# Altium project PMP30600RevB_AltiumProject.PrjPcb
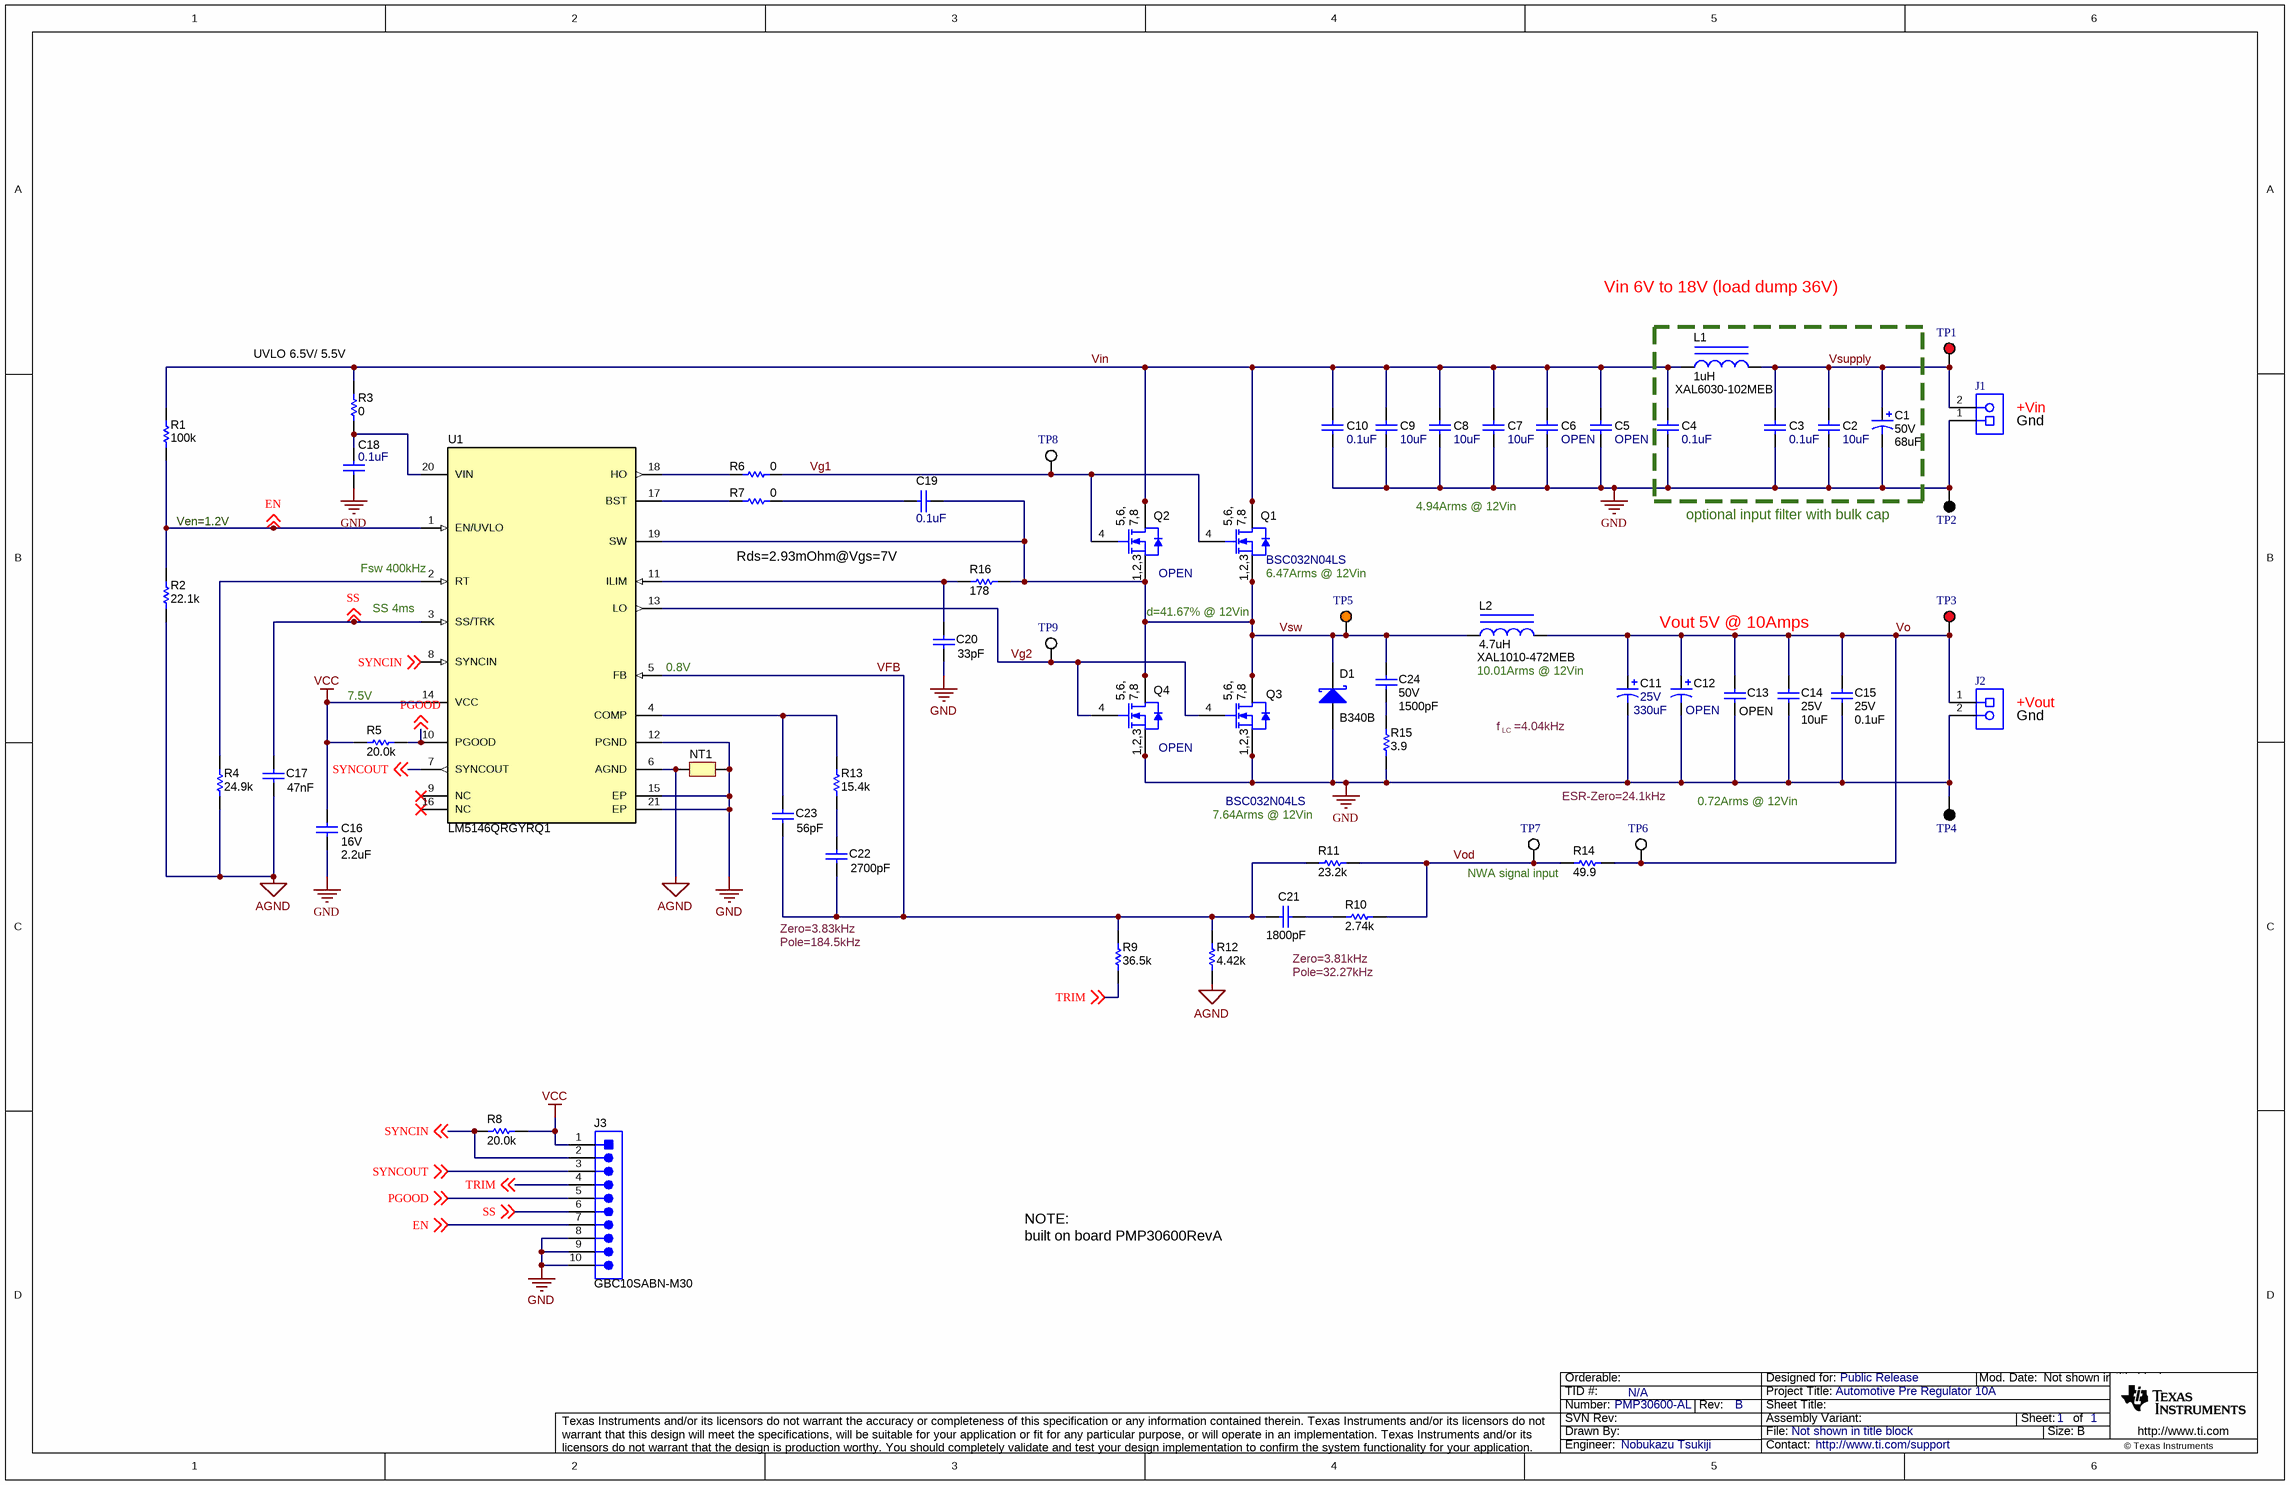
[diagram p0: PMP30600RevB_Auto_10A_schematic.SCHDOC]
TID: N/A; TechSupport: http://www.ti.com/support; SCH_Rev: B; PRJ_Title: Automotive Pre Regulator 10A; PRJ_Number: PMP30600-AL; PRJ_Engineer: Nobukazu Tsukiji; PRJ_Customer: Public Release; PCB_Rev: A; PCB_Layout: Who did the Layout?
1 sheet, 61 parts. Net scope: global (net labels, ports and power ports of the same name join across sheets).
Board file: PMP30600RevA_board.PcbDoc

## Sheet PMP30600RevB_Auto_10A_schematic.SCHDOC
size 431 x 279 mm; Date: Not shown in title block; ApprovedBy: Not shown in title block; CheckedBy: Not shown in title block; Author: Not shown in title block; CompanyName: Not shown in title block; Engineer: Not shown in title block; Organization: Not shown in title block; Address1: Not shown in title block; Address2: Not shown in title block; Address3: Not shown in title block; Address4: Not shown in title block; DocumentNumber: 1; Revision: Use project parameter SCH_Rev; SheetNumber: 1; SheetTotal: 1; PageSetup: Record=PageOptions¦CenterHorizontal=True¦CenterVertical=True¦PrintScale=0.70¦XCorrection=1.00¦YCorrection=1.00¦PrintKind=0¦BorderSize=5000000¦LeftOffset=0¦BottomOffset=0¦Orientation=2¦PaperLength=1000¦PaperWidth=1000¦Scale=100¦PaperSource=15¦PrintQuality=600¦MediaType=1¦DitherType=10¦PaperKind=A4¦PrintScaleMode=1

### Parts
C1  VDC_V: 50V  ValueDisplayed: 68uF  [SM_RADIAL_8MM]  (hidden comment: EEHZC1H680P)
C2  ValueDisplayed: 10uF  [1210_270]  (hidden comment: Capacitor)
C3  ValueDisplayed: 0.1uF  [0603]  (hidden comment: Capacitor)
C4  ValueDisplayed: 0.1uF  [0603]  (hidden comment: Capacitor)
C5  ValueDisplayed: OPEN  [1210_270]  (hidden comment: Capacitor)
C6  ValueDisplayed: OPEN  [1210_270]  (hidden comment: Capacitor)
C7  ValueDisplayed: 10uF  [1210_270]  (hidden comment: Capacitor)
C8  ValueDisplayed: 10uF  [1210_270]  (hidden comment: Capacitor)
C9  ValueDisplayed: 10uF  [1210_270]  (hidden comment: Capacitor)
C10  ValueDisplayed: 0.1uF  [0603]  (hidden comment: Capacitor)
C11  VDC_V: 25V  ValueDisplayed: 330uF  [SM_RADIAL_10BMM]  (hidden comment: EEHZC1E331P)
C12  ValueDisplayed: OPEN  [SM_RADIAL_10BMM]  (hidden comment: EEHZC1E331P)
C13  VDC_V: OPEN  [1210_220]  (hidden comment: GRM32DR71E106KA12L)
C14  VDC_V: 25V  ValueDisplayed: 10uF  [1210_220]  (hidden comment: GRM32DR71E106KA12L)
C15  VDC_V: 25V  ValueDisplayed: 0.1uF  [0603]  (hidden comment: GRM188R71E104KA01D)
C16  VDC_V: 16V  ValueDisplayed: 2.2uF  [0805_HV]  (hidden comment: GRM21BR71C225KA12L)
C17  ValueDisplayed: 47nF  [0603]  (hidden comment: GRM188R71E473KA01D)
C18  ValueDisplayed: 0.1uF  [0603]  (hidden comment: Capacitor)
C19  ValueDisplayed: 0.1uF  [0603]  (hidden comment: Capacitor)
C20  ValueDisplayed: 33pF  [0603]  (hidden comment: GRM1885C1H330JA01D)
C21  ValueDisplayed: 1800pF  [0603]  (hidden comment: GRM1885C1H182JA01D)
C22  ValueDisplayed: 2700pF  [0603]  (hidden comment: GRM1885C1H272JA01D)
C23  ValueDisplayed: 56pF  [0603]  (hidden comment: GRM1885C1H560JA01D)
C24  VDC_V: 50V  ValueDisplayed: 1500pF  [0603]  (hidden comment: GRM188R71H152KA01D)
D1  PartNumberDisplayed: B340B  [SMB]  (hidden comment: B340B-13-F)
J1  691214110002  [Wurth_691214110002]  (value not drawn)
J2  691236510002  [Wurth_691236510002]  (value not drawn)
J3  GBC10SABN-M30  [Sullins_GBC10SABN-M30]
L1  XAL6030-102MEB  ValueDisplayed: 1uH  [XAL6030]
L2  XAL1010-472MEB  ValueDisplayed: 4.7uH  [XAL1010]
NT1  Net-Tie  [Net-Tie_10milWide_30milLong]  (value not drawn)  (net tie, no BOM)
Q1  BSC032N04LS  [PG-TDSON-8]
Q2  OPEN  [PG-TDSON-8]
Q3  PartNumber: BSC032N04LS  [PG-TDSON-8]  (hidden comment: MOSFET_N_D56789G4S123)
Q4  OPEN  [PG-TDSON-8]
R1  ValueDisplayed: 100k  [0603]  (hidden comment: CRCW0603100KFKEA)
R2  ValueDisplayed: 22.1k  [0603]  (hidden comment: CRCW060322K1FKEA)
R3  ValueDisplayed: 0  [0603]  (hidden comment: RMCF0603ZT0R00)
R4  ValueDisplayed: 24.9k  [0603]  (hidden comment: CRCW060324K9FKEA)
R5  ValueDisplayed: 20.0k  [0603]  (hidden comment: CRCW060320K0FKEA)
R6  ValueDisplayed: 0  [0603]  (hidden comment: RMCF0603ZT0R00)
R7  ValueDisplayed: 0  [0603]  (hidden comment: RMCF0603ZT0R00)
R8  ValueDisplayed: 20.0k  [0603]  (hidden comment: CRCW060320K0FKEA)
R9  ValueDisplayed: 36.5k  [0603]  (hidden comment: RC0603FR-0736K5L)
R10  ValueDisplayed: 2.74k  [0603]  (hidden comment: CRCW06032K74FKEA)
R11  ValueDisplayed: 23.2k  [0603]  (hidden comment: CRCW060323K2FKEA)
R12  ValueDisplayed: 4.42k  [0603]  (hidden comment: CRCW06034K42FKEA)
R13  ValueDisplayed: 15.4k  [0603]  (hidden comment: CRCW060315K4FKEA)
R14  ValueDisplayed: 49.9  [0603]  (hidden comment: CRCW060349R9FKEA)
R15  ValueDisplayed: 3.9  [0805_HV]  (hidden comment: CRCW08053R90JNEA)
R16  ValueDisplayed: 178  [0603]  (hidden comment: CRCW0603178RFKEA)
TP1  5000  [Keystone5000]  (value not drawn)
TP2  5001  [Keystone5001]  (value not drawn)
TP3  5000  [Keystone5000]  (value not drawn)
TP4  5001  [Keystone5001]  (value not drawn)
TP5  5003  [Keystone5003]  (value not drawn)
TP6  5002  [Keystone5002]  (value not drawn)
TP7  5002  [Keystone5002]  (value not drawn)
TP8  5002  [Keystone5002]  (value not drawn)
TP9  5002  [Keystone5002]  (value not drawn)
U1  LM5146QRGYRQ1  [RGY0020B]

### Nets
AGND: C17.2 NT1.1 R2.1 R4.1 R12.1 U1.6(AGND)
GND: C1.2(-) C2.2 C3.2 C4.2 C5.2 C6.2 C7.2 C8.2 C9.2 C10.2 C11.2(-) C12.2(-) C13.2 C14.2 C15.2 C16.2 C18.2 C20.2 D1.2(A) J1.1 J2.2 J3.8 J3.9 J3.10 NT1.2 Q3.1(S) Q3.2(S) Q3.3(S) Q4.1(S) Q4.2(S) Q4.3(S) R15.1 TP2.1 TP4.1 U1.12(PGND) U1.15(EP) U1.21(EP)
VCC: C16.1 J3.1 R5.1 R8.2 U1.14(VCC)
EN: J3.7 R1.1 R2.2 U1.1(EN/UVLO) ; off-sheet EN
PGOOD: J3.5 R5.2 U1.10(PGOOD) ; off-sheet PGOOD
SS: C17.1 J3.6 U1.3(SS/TRK) ; off-sheet SS
SYNCIN: J3.2 R8.1 U1.8(SYNCIN) ; off-sheet SYNCIN
SYNCOUT: J3.3 U1.7(SYNCOUT) ; off-sheet SYNCOUT
TRIM: J3.4 R9.1 ; off-sheet TRIM
VFB: C21.2 C22.1 C23.1 R9.2 R11.1 R12.2 U1.5(FB)
Vg1: Q1.4(G) Q2.4(G) R6.2 TP8.1
Vg2: Q3.4(G) Q4.4(G) TP9.1 U1.13(LO)
Vin: C4.1 C5.1 C6.1 C7.1 C8.1 C9.1 C10.1 L1.1 Q1.5(D) Q1.6(D) Q1.7(D) Q1.8(D) Q1.9(D) Q2.5(D) Q2.6(D) Q2.7(D) Q2.8(D) Q2.9(D) R1.2 R3.2
Vo: C11.1(+) C12.1(+) C13.1 C14.1 C15.1 J2.1 L2.2 R14.2 TP3.1 TP6.1
Vod: R10.2 R11.2 R14.1 TP7.1
Vsupply: C1.1(+) C2.1 C3.1 J1.2 L1.2 TP1.1
Vsw: C19.2 C24.1 D1.1(K) L2.1 Q1.1(S) Q1.2(S) Q1.3(S) Q2.1(S) Q2.2(S) Q2.3(S) Q3.5(D) Q3.6(D) Q3.7(D) Q3.8(D) Q3.9(D) Q4.5(D) Q4.6(D) Q4.7(D) Q4.8(D) Q4.9(D) R16.2 TP5.1 U1.19(SW)
NetC18_1: C18.1 R3.1 U1.20(VIN)
NetC19_1: C19.1 R7.2
NetC20_1: C20.1 R16.1 U1.11(ILIM)
NetC21_1: C21.1 R10.1
NetC22_2: C22.2 R13.2
NetC23_2: C23.2 R13.1 U1.4(COMP)
NetC24_2: C24.2 R15.2
NetR4_2: R4.2 U1.2(RT)
NetR6_1: R6.1 U1.18(HO)
NetR7_1: R7.1 U1.17(BST)

Not connected (* = marked no-connect by the designer): U1 9(NC)* 16(NC)*

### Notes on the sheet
- Vin 6V to 18V (load dump 36V)
- (near R3) UVLO 6.5V/ 5.5V
- (near J1) +Vin
- (near J1) Gnd
- Ven=1.2V
- (near U1) Fsw 400kHz
- Rds=2.93mOhm@Vgs=7V
  ILIM=13A
- 4.94Arms @ 12Vin
- (near TP2) optional input filter with bulk cap
- (near U1) SS 4ms
- d=41.67% @ 12Vin
- (near Q1) 6.47Arms @ 12Vin
- Vout 5V @ 10Amps
- (near R5) 7.5V
- (near U1) 0.8V
- (near L2) 10.01Arms @ 12Vin
- (near J2) +Vout
- LC
- f    =4.04kHz
- (near J2) Gnd
- (near R11) 7.64Arms @ 12Vin
- ESR-Zero=24.1kHz
- 0.72Arms @ 12Vin
- NWA signal input
- Zero=3.83kHz
- Pole=184.5kHz
- Zero=3.81kHz
- Pole=32.27kHz
- built on board PMP30600RevA
- NOTE:

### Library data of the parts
C1 = CMP-0012599-3: CAP, Polymer Hybrid, 68 uF, 50 V, +/- 20%, 30 ohm, 8x10 SMD; Manufacturer: Panasonic; TaMin_C: -55°C; ESR_ohm: 30; Polarized: Y; SizeAreaWB_mm2: 113.3; Value1: 30 ohm; Value: 68uF; TaMax_C: 125°C; SizeZ_mm: 10.2; SizeX_mm: 9; SizeY_mm: 8.3; SizeArea_mm2: 74.7; CompType: Capacitor; Cap_F: 68µF; IRMS_A: 1.25A; AEC Category: Q200
C2 C5-C9 = CMP-0009226-3: CAP, CERM, 10 uF, 50 V, +/- 10%, X7R, 1210; PartNumber: GRM32ER71H106KA12L; Manufacturer: MuRata; Polarized: N; Value: 10uF; U/M: EA; Cap_F: 10µF; Value1: Unknown; VDC_V: 50V; TaMin_C: -55°C; TaMax_C: 125°C; Cap_Case: 1210; SizeArea_mm2: 8; SizeAreaWB_mm2: 14.7; SizeX_mm: 3.2; SizeY_mm: 2.5; SizeZ_mm: 2.7; AEC Category: Q200
C3 C4 C10 C18 C19 = CMP-0007434-4: CAP, CERM, 0.1 uF, 50 V, +/- 10%, X7R, 0603; PartNumber: GRM188R71H104KA93D; Manufacturer: MuRata; Polarized: N; Value: 0.1uF; U/M: EA; Cap_F: 100nF; Value1: Unknown; VDC_V: 50V; TaMin_C: -55°C; TaMax_C: 125°C; SizeArea_mm2: 1.28; SizeAreaWB_mm2: 4.68; SizeX_mm: 1.6; SizeY_mm: 0.8; SizeZ_mm: 1; AEC Category: Q200
C11 = CMP-0012593-1: CAP, Polymer Hybrid, 330 uF, 25 V, +/- 20%, 20 ohm, 10x10 SMD; Manufacturer: Panasonic; TaMin_C: -55°C; ESR_ohm: 20; Polarized: Y; SizeAreaWB_mm2: 159.9; Value1: 20 ohm; U/M: EA; Value: 330uF; TaMax_C: 125°C; SizeZ_mm: 10.2; SizeX_mm: 11; SizeY_mm: 10.3; SizeArea_mm2: 113.3; CompType: Capacitor; Cap_F: 330µF; IRMS_A: 2A; AEC Category: Q200
C12 = CMP-0012593-1: CAP, Polymer Hybrid, 330 uF, 25 V, +/- 20%, 20 ohm, 10x10 SMD; Manufacturer: Panasonic; TaMin_C: -55°C; ESR_ohm: 20; Polarized: Y; SizeAreaWB_mm2: 159.9; Value1: 20 ohm; U/M: EA; Value: 330uF; TaMax_C: 125°C; SizeZ_mm: 10.2; SizeX_mm: 11; SizeY_mm: 10.3; Value2: 25V; SizeArea_mm2: 113.3; CompType: Capacitor; Cap_F: 330µF; IRMS_A: 2A; AEC Category: Q200
C13 = CMP-0009190-1: CAP, CERM, 10 uF, 25 V, +/- 10%, X7R, 1210; Manufacturer: MuRata; TaMin_C: -55°C; Polarized: N; SizeAreaWB_mm2: 14.7; Value1: Unknown; U/M: EA; Value: 10uF; TaMax_C: 125°C; SizeZ_mm: 2.2; SizeX_mm: 3.2; SizeY_mm: 2.5; Cap_Case: 1210; Value2: 25V; SizeArea_mm2: 8; Cap_F: 10µF; AEC Category: Q200
C14 = CMP-0009190-1: CAP, CERM, 10 uF, 25 V, +/- 10%, X7R, 1210; Manufacturer: MuRata; TaMin_C: -55°C; Polarized: N; SizeAreaWB_mm2: 14.7; Value1: Unknown; U/M: EA; Value: 10uF; TaMax_C: 125°C; SizeZ_mm: 2.2; SizeX_mm: 3.2; SizeY_mm: 2.5; Cap_Case: 1210; SizeArea_mm2: 8; Cap_F: 10µF; AEC Category: Q200
C15 = CMP-0007404-4: CAP, CERM, 0.1 uF, 25 V, +/- 10%, X7R, 0603; Manufacturer: MuRata; TaMin_C: -55°C; Polarized: N; SizeAreaWB_mm2: 4.68; Value1: Unknown; U/M: EA; Value: 0.1uF; TaMax_C: 125°C; SizeZ_mm: 1; SizeX_mm: 1.6; SizeY_mm: 0.8; SizeArea_mm2: 1.28; Cap_F: 100nF; AEC Category: Q200
C16 = CMP-0008329-2: CAP, CERM, 2.2 uF, 16 V, +/- 10%, X7R, 0805; Manufacturer: MuRata; TaMin_C: -55°C; ESR_ohm: 4m; Polarized: N; SizeAreaWB_mm2: 6.75; Value1: 0.004 ohm; U/M: EA; Value: 2.2uF; TaMax_C: 125°C; SizeZ_mm: 1.45; SizeX_mm: 2; SizeY_mm: 1.25; Cap_Case: 0805; SizeArea_mm2: 2.5; Cap_F: 2.2µF; AEC Category: Q200
C17 = CMP-0007423-4: CAP, CERM, 0.047 uF, 25 V, +/- 10%, X7R, 0603; Manufacturer: MuRata; TaMin_C: -55°C; Polarized: N; SizeAreaWB_mm2: 4.68; Value1: Unknown; U/M: EA; TaMax_C: 125°C; SizeZ_mm: 1; SizeX_mm: 1.6; SizeY_mm: 0.8; Value2: 25V; SizeArea_mm2: 1.28; AEC Category: Q200
C20 = CMP-0007208-4: CAP, CERM, 33 pF, 50 V, +/- 5%, C0G/NP0, 0603; Manufacturer: MuRata; TaMin_C: -55°C; Polarized: N; SizeAreaWB_mm2: 4.68; Value1: Unknown; U/M: EA; Value: 33pF; TaMax_C: 125°C; SizeZ_mm: 1; SizeX_mm: 1.6; SizeY_mm: 0.8; Value2: 50V; SizeArea_mm2: 1.28; AEC Category: Q200
C21 = CMP-0007192-4: CAP, CERM, 1800 pF, 50 V, +/- 5%, C0G/NP0, 0603; Manufacturer: MuRata; TaMin_C: -55°C; Polarized: N; SizeAreaWB_mm2: 4.68; Value1: Unknown; U/M: EA; Value: 1800pF; TaMax_C: 125°C; SizeZ_mm: 1; SizeX_mm: 1.6; SizeY_mm: 0.8; Value2: 50V; SizeArea_mm2: 1.28; Cap_F: 1.8nF; AEC Category: Q200
C22 = CMP-0007204-4: CAP, CERM, 2700 pF, 50 V, +/- 5%, C0G/NP0, 0603; Manufacturer: MuRata; TaMin_C: -55°C; Polarized: N; SizeAreaWB_mm2: 4.68; Value1: Unknown; U/M: EA; Value: 2700pF; TaMax_C: 125°C; SizeZ_mm: 1; SizeX_mm: 1.6; SizeY_mm: 0.8; Value2: 50V; SizeArea_mm2: 1.28; Cap_F: 2.7nF; AEC Category: Q200
C23 = CMP-0007224-4: CAP, CERM, 56 pF, 50 V, +/- 5%, C0G/NP0, 0603; Manufacturer: MuRata; TaMin_C: -55°C; Polarized: N; SizeAreaWB_mm2: 4.68; Value1: Unknown; U/M: EA; Value: 56pF; TaMax_C: 125°C; SizeZ_mm: 1; SizeX_mm: 1.6; SizeY_mm: 0.8; Value2: 50V; SizeArea_mm2: 1.28; AEC Category: Q200
C24 = CMP-0007437-1: CAP, CERM, 1500 pF, 50 V, +/- 10%, X7R, 0603; Manufacturer: MuRata; TaMin_C: -55°C; Polarized: N; SizeAreaWB_mm2: 4.68; Value1: Unknown; U/M: EA; Value: 1500pF; TaMax_C: 125°C; SizeZ_mm: 1; SizeX_mm: 1.6; SizeY_mm: 0.8; SizeArea_mm2: 1.28; Cap_F: 1.5nF; AEC Category: Q200
D1 = CMP-0028412-2: Diode, Schottky, 40 V, 3 A, SMB; Manufacturer: Diodes Inc.; SizeArea_mm2: 21.336; Vr_V: 40V; Value: 40V; Value2: 0.5V; Vf_V: 500mV; TJmax_C: 125°C; RJC_CperW: 25; SizeX_mm: 5.6; AEC Category: Q101; SizeY_mm: 3.81; Value1: 3A; SizeZ_mm: 2.6; SizeAreaWB_mm2: 44.156; Green_Lifecycle: Active; Green_REACh: Passed
J1 = CMP-0054825-2: Terminal Block, 3.5mm, 2x1, Tin, TH; Manufacturer: Wurth Elektronik; Pitch_mm: 3.5; CT: TRUE; CNHeader: FALSE; Voltage_V: 300V; Gender: Female; Cert_UL: Y; Row_Count: 1; Current_A: 10A
J2 = CMP-0079044-1: Terminal Block, 5.08mm, 2x1, R/A, TH; Manufacturer: Wurth Elektronik; Pitch_mm: 5.08; Cert_VDE: Y; Gender: Female; Voltage_V: 300V; Current_A: 20A; Row_Count: 1
J3 = CMP-0054626-1: Header, 2.54mm, 10x1, Gold, SMT; Manufacturer: Sullins Connector Solutions; CNHeader: TRUE; Current_A: 3A; Shrouded: N; Gender: Male; Voltage_V: 600V; Row_Count: 1; Pitch_mm: 2.54; CT: FALSE; Cert_UL: Y
L1 = CMP-0061011-1: Inductor, Shielded, Composite, 1 uH, 21.5 A, 0.01 ohm, SMD; Manufacturer: Coilcraft; Isat: 23A @ 30% inductance drop; Irms: 21.5A @ 40C rise; Green_Lifecycle: Not Set; SizeAreaWB_mm2: 71.5616; DCR_ohm: 0.01; Green_REACh: Incomplete; Value: 1uH; Imax_A: 21.5A; SizeZ_mm: 3.1; SizeX_mm: 6.36; SizeY_mm: 6.56; SizeArea_mm2: 41.7216; Ind_H: 1µH; AEC Category: Q200
L2 = CMP-0060950-1: Inductor, Shielded, Composite, 4.7 uH, 24 A, 0.01 ohm, SMD; Manufacturer: Coilcraft; Isat: 25.4A @ 30% inductance drop; Green_Lifecycle: Not Set; SizeAreaWB_mm2: 159.6; DCR_ohm: 0.01; Green_REACh: Incomplete; Irms: 24A @ 40C rise; Value: 4.7uH; Imax_A: 24A; SizeZ_mm: 10; SizeX_mm: 11.3; SizeArea_mm2: 113; Ind_H: 4.7µH; AEC Category: Q200
NT1 = CMP-0078142-1: Single point connection between nets.
Q1 Q3 = CMP-0000689-1: MOSFET, N-CH, 40 V, 73 A, PG-TDSON-8; Manufacturer: Infineon Technologies; Alternate Manufacturer: None; U/M: EA; ChType: N; Value: 40V; Value1: 0.008; Rdson45_ohm: 8.5m; Value2: 30 nC; QgTyp_nC: 30; Vgs_V: 20V; IdsMax_A: 73A; SizeAreaWB_mm2: 55.131; SizeArea_mm2: 29.351; SizeX_mm: 5.99; SizeY_mm: 4.9; SizeZ_mm: 1.12; AEC Category: Q101
Q2 Q4 = CMP-0000689-1: MOSFET, N-CH, 40 V, 73 A, PG-TDSON-8; PartNumber: BSC032N04LS; Manufacturer: Infineon Technologies; Alternate Manufacturer: None; U/M: EA; ChType: N; Value: 40V; Value1: 0.008; Rdson45_ohm: 8.5m; Value2: 30 nC; QgTyp_nC: 30; Vgs_V: 20V; IdsMax_A: 73A; SizeAreaWB_mm2: 55.131; SizeArea_mm2: 29.351; SizeX_mm: 5.99; SizeY_mm: 4.9; SizeZ_mm: 1.12; AEC Category: Q101
R1 = CMP-0021990-4: RES, 100 k, 1%, 0.1 W, AEC-Q200 Grade 0, 0603; Manufacturer: Vishay-Dale; Power_W: 100mW; TempCo: 100 ppm/C; Value: 100k; EIA_Code: E96; SizeX_mm: 1.6; SizeY_mm: 0.8; SizeZ_mm: 1; Value2: 0.1W; SizeArea_mm2: 1.28; AEC Qualified: Y; VDC_V: 75V; AEC Category: Q200; AEC Grade: 0
R2 = CMP-0022220-4: RES, 22.1 k, 1%, 0.1 W, AEC-Q200 Grade 0, 0603; Manufacturer: Vishay-Dale; Power_W: 100mW; TempCo: 100 ppm/C; Value_Code: 22k1; Value: 22.1k; EIA_Code: E96; SizeX_mm: 1.6; SizeY_mm: 0.8; SizeZ_mm: 1; Value2: 0.1W; SizeArea_mm2: 1.28; AEC Qualified: Y; VDC_V: 75V; AEC Category: Q200; AEC Grade: 0
R3 R6 R7 = CMP-0023343-1: RES, 0, 1%, 0.1 W, AEC-Q200 Grade 0, 0603; Manufacturer: Stackpole Electronics Inc; Power_W: 100mW; TempCo: ppm/C; U/M: EA; Value: 0; SizeX_mm: 1.6; SizeY_mm: 0.8; SizeZ_mm: 1; Value2: 0.1W; SizeArea_mm2: 1.28; AEC Qualified: Y; AEC Category: Q200
R4 = CMP-0022237-3: RES, 24.9 k, 1%, 0.1 W, 0603; Manufacturer: Vishay-Dale; Power_W: 100mW; TempCo: 100 ppm/C; Value_Code: 24k9; U/M: EA; Value: 24.9k; EIA_Code: E96; SizeX_mm: 1.6; SizeY_mm: 0.8; SizeZ_mm: 1; Value2: 0.1W; SizeArea_mm2: 1.28; VDC_V: 75V; AEC Category: Q200
R5 R8 = CMP-0022204-1: RES, 20.0 k, 1%, 0.1 W, 0603; Manufacturer: Vishay-Dale; Power_W: 100mW; TempCo: 100 ppm/C; Value_Code: 20k0; U/M: EA; Value: 20.0k; EIA_Code: E96; Res_ohm: 20k; SizeX_mm: 1.6; SizeY_mm: 0.8; SizeZ_mm: 1; Value2: 0.1W; SizeArea_mm2: 1.28; VDC_V: 75V; AEC Category: Q200
R9 = CMP-0023056-1: RES, 36.5 k, 1%, 0.1 W, 0603; Manufacturer: Yageo America; Power_W: 100mW; TempCo: 200 ppm/C; Value_Code: 36k5; U/M: EA; Value: 36.5k; EIA_Code: E96; SizeX_mm: 1.6; SizeY_mm: 0.8; SizeZ_mm: 1; Value2: 0.1W; SizeArea_mm2: 1.28; VDC_V: 150V; AEC Category: Q200
R10 = CMP-0022281-4: RES, 2.74 k, 1%, 0.1 W, AEC-Q200 Grade 0, 0603; Manufacturer: Vishay-Dale; Power_W: 100mW; TempCo: 100 ppm/C; Value_Code: 2k74; Value: 2.74k; EIA_Code: E96; SizeX_mm: 1.6; SizeY_mm: 0.8; SizeZ_mm: 1; Value2: 0.1W; SizeArea_mm2: 1.28; AEC Qualified: Y; VDC_V: 75V; AEC Category: Q200; AEC Grade: 0
R11 = CMP-0022228-3: RES, 23.2 k, 1%, 0.1 W, 0603; Manufacturer: Vishay-Dale; Power_W: 100mW; TempCo: 100 ppm/C; Value_Code: 23k2; U/M: EA; Value: 23.2k; EIA_Code: E96; SizeX_mm: 1.6; SizeY_mm: 0.8; SizeZ_mm: 1; Value2: 0.1W; SizeArea_mm2: 1.28; VDC_V: 75V; AEC Category: Q200
R12 = CMP-0022453-3: RES, 4.42 k, 1%, 0.1 W, 0603; Manufacturer: Vishay-Dale; Power_W: 100mW; TempCo: 100 ppm/C; Value_Code: 4k42; U/M: EA; Value: 4.42k; EIA_Code: E96; SizeX_mm: 1.6; SizeY_mm: 0.8; SizeZ_mm: 1; Value2: 0.1W; SizeArea_mm2: 1.28; VDC_V: 75V; AEC Category: Q200
R13 = CMP-0022067-3: RES, 15.4 k, 1%, 0.1 W, 0603; Manufacturer: Vishay-Dale; Power_W: 100mW; TempCo: 100 ppm/C; Value_Code: 15k4; U/M: EA; Value: 15.4k; EIA_Code: E96; SizeX_mm: 1.6; SizeY_mm: 0.8; SizeZ_mm: 1; Value2: 0.1W; SizeArea_mm2: 1.28; VDC_V: 75V; AEC Category: Q200
R14 = CMP-0022448-3: RES, 49.9, 1%, 0.1 W, 0603; Manufacturer: Vishay-Dale; Power_W: 100mW; TempCo: 100 ppm/C; Value_Code: 49R9; U/M: EA; Value: 49.9; EIA_Code: E96; SizeX_mm: 1.6; SizeY_mm: 0.8; SizeZ_mm: 1; Value2: 0.1W; SizeArea_mm2: 1.28; VDC_V: 75V; AEC Category: Q200
R15 = CMP-0020549-3: RES, 3.9, 5%, 0.125 W, AEC-Q200 Grade 0, 0805; Manufacturer: Vishay-Dale; Power_W: 125mW; TempCo: 200 ppm/C; Value_Code: 3R90; Value: 3.9; EIA_Code: E24; SizeX_mm: 2; SizeY_mm: 1.25; SizeZ_mm: 1.45; Value2: 0.125W; SizeArea_mm2: 2.5; AEC Qualified: Y; VDC_V: 150V; AEC Category: Q200; AEC Grade: 0
R16 = CMP-0022088-4: RES, 178, 1%, 0.1 W, 0603; Manufacturer: Vishay-Dale; Power_W: 100mW; TempCo: 100 ppm/C; Value_Code: 178R; U/M: EA; Value: 178; EIA_Code: E96; SizeX_mm: 1.6; SizeY_mm: 0.8; SizeZ_mm: 1; Value2: 0.1W; SizeArea_mm2: 1.28; VDC_V: 75V; AEC Category: Q200
TP1 TP3 = CMP-0055137-1: Test Point, Miniature, Red, TH; Manufacturer: Keystone; CNHeader: FALSE; ContactFinish: Silver; CT: TRUE; Green_Lifecycle: Active; Green_REACh: Passed
TP2 TP4 = CMP-0055138-1: Test Point, Miniature, Black, TH; Manufacturer: Keystone; CNHeader: FALSE; ContactFinish: Silver; CT: TRUE; Green_Lifecycle: Active; Green_REACh: Passed
TP5 = CMP-0055140-1: Test Point, Miniature, Orange, TH; Manufacturer: Keystone; CNHeader: FALSE; ContactFinish: Silver; CT: TRUE; Green_Lifecycle: Active; Green_REACh: Passed
TP6-TP9 = CMP-0055139-1: Test Point, Miniature, White, TH; Manufacturer: Keystone; CNHeader: FALSE; ContactFinish: Silver; CT: TRUE; Green_Lifecycle: Active; Green_REACh: Passed
U1 = CMP-0081848-1: 5.5-V to 100-V Synchronous Buck Controller With Wide Duty Cycle Range, RGY0020B (VQFN-20); Alternate PartNumber: LM5146QRGYTQ1; Alternate Manufacturer: Texas Instruments; SizeAreaWB_mm2: 24.75; SizeZ_mm: 1; SizeX_mm: 3.5; SizeY_mm: 4.5; SizeArea_mm2: 15.75; CompType: IC; AEC Qualified: Y; AEC Category: Q200

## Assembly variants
001: not fitted FID1 FID2 FID3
